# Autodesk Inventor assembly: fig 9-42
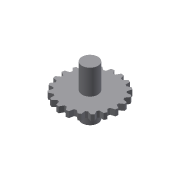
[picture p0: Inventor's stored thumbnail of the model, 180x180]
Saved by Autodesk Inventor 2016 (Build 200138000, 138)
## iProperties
Created: 2013-07
Part Number: fig 9-42
Document SubType Name: Assembly
Designer: CADCIM
Author: CADCIM
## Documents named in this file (3)
- D:\KAVITA\Autodesk Inventor_ 2016 Project_Kavita\Inventor_Part Files\Inventor_2016_Part\c09_Inv_2016\c09_inv_2016_prt\fig 9-42.iam
- D:\KAVITA\Autodesk Inventor_ 2016 Project_Kavita\Inventor_Part Files\Inventor_2016_Part\c09_Inv_2016\c09_inv_2016_prt\13.ipt
- D:\KAVITA\Autodesk Inventor_ 2016 Project_Kavita\Inventor_Part Files\Inventor_2016_Part\c09_Inv_2016\c09_inv_2016_prt\14.ipt
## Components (2 placed, 2 different names)
1. 13:1 — Rotational:1
2. 14:1 — Rotational:1
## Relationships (1: RevoluteJoint 1)
- Rotational:1 [RevoluteJoint]: 13:1 ↔ 14:1
